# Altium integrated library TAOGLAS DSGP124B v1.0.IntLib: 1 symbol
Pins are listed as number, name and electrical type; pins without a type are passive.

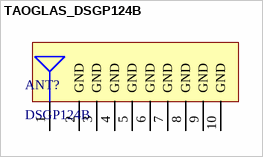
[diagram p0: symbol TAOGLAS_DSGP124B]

## TAOGLAS_DSGP124B
designator ANT?, comment DSGP124B
GPS L1 / GALILEO E1 1575.42MHz 12*12*4mm Ceramic Patch SMD Antenna; ComponentLibStatus: Created; MFG: Taoglas; Temp_High: +85C; Temp_Low: -40C
footprint TAOGLAS_DSGP124B (GPS L1 / GALILEO E1 1575.42MHz 12*12*4mm Ceramic Patch SMD Antenna)
pins: 1 RF FEED, 2 GND, 3 GND, 4 GND, 5 GND, 6 GND, 7 GND, 8 GND, 9 GND, 10 GND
